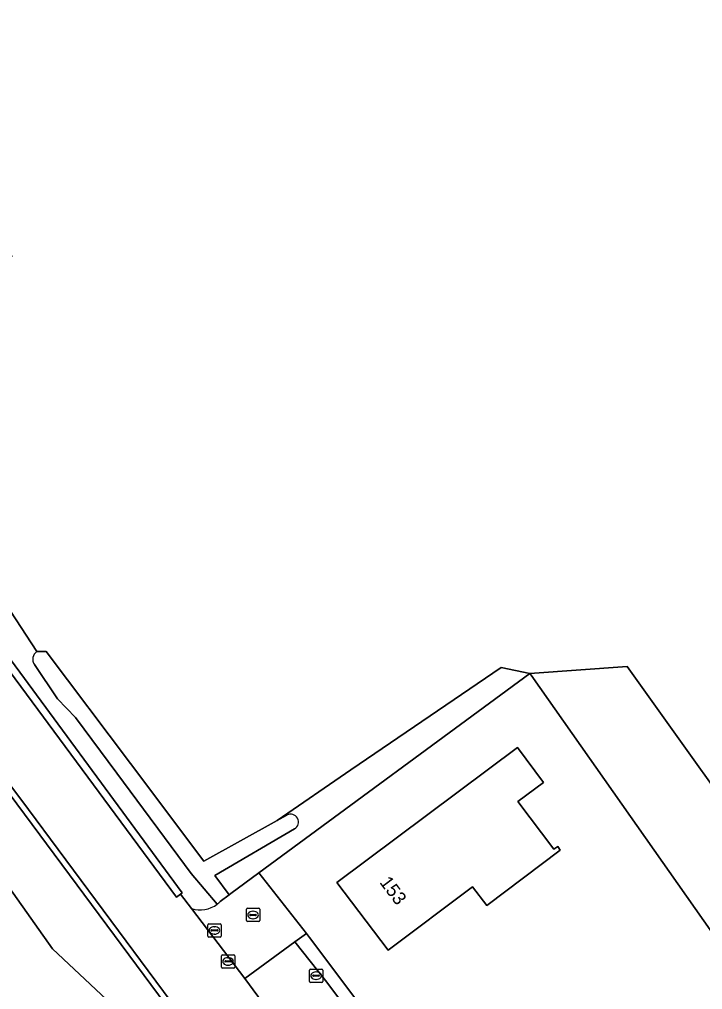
# Model space of a CAD drawing. Extents: x 164494 to 166241, y 382475 to 384495.
# Drawn here: x 164967.7 to 165019, y 383260.4 to 383333.2 of the extents above; entities that cross this region are included whole.
import ezdxf

# ---------------------------------------------------------------- set-up
doc = ezdxf.new("R2010")
doc.units = 0
for name, color, linetype in [('IMGEO_Berm_halfverhard', 7, 'Continuous'), ('IMGEO_Bouwland', 7, 'Continuous'), ('IMGEO_Brandkraan', 7, 'Continuous'), ('IMGEO_Erf', 7, 'Continuous'), ('IMGEO_Grasland_overig', 7, 'Continuous'), ('IMGEO_Groenvoorziening', 7, 'Continuous'), ('IMGEO_Kolk', 7, 'Continuous'), ('IMGEO_Pand', 7, 'Continuous'), ('IMGEO_Pand_nummerreeks', 7, 'Continuous'), ('IMGEO_Parkeervlak_open', 7, 'Continuous'), ('IMGEO_Rijbaan_lokaal_gesloten', 7, 'Continuous'), ('IMGEO_Rioolput', 7, 'Continuous'), ('IMGEO_Voetpad_open', 7, 'Continuous'), ('IMGEO_Waterloop', 7, 'Continuous')]:
    doc.layers.add(name, color=color, linetype=linetype)

msp = doc.modelspace()

# ---------------------------------------------------------------- linework, layer by layer
at = {"layer": 'IMGEO_Berm_halfverhard'}
for points in [[(164963.99, 383288.228), (164979.462, 383267.349), (164979.765, 383267.573), (164979.896, 383267.671), (164964.472, 383288.585)], [(164958.624, 383286.837), (164958.165, 383286.487), (164958.551, 383285.995), (164958.685, 383286.071), (164960.201, 383284.12), (164981.497, 383255.445), (165004.699, 383224.274), (165010.162, 383216.934), (165012.663, 383213.574), (165041.519, 383174.67), (165059.934, 383149.875), (165074.189, 383130.821), (165074.54, 383131.069), (165010.834, 383216.638), (165007.308, 383221.332), (165004.939, 383224.601), (164967.779, 383274.687)]]:
    msp.add_lwpolyline(points, close=True, dxfattribs=at)
at = {"layer": 'IMGEO_Bouwland'}
msp.add_lwpolyline([(164957.606, 383341.995), (164967.101, 383315.443), (164955.054, 383305.726), (164967.059, 383289.542), (164967.017, 383288.822), (164968.991, 383285.777), (164969.684, 383285.794), (164976.01, 383277.378), (164981.526, 383270.039), (164987.027, 383273.084), (164992.552, 383276.899), (165003.844, 383284.575), (165005.994, 383284.124), (165013.312, 383284.652), (165024.637, 383268.794)], dxfattribs=at)
at = {"layer": 'IMGEO_Brandkraan'}
for p, q in [((164989.523, 383261.941), (164990.375, 383261.941)), ((164989.448, 383261.015), (164989.448, 383261.867)), ((164989.707, 383261.435), (164989.707, 383261.447)), ((164990.145, 383261.398), (164989.747, 383261.398)), ((164989.75, 383261.484), (164990.148, 383261.484)), ((164989.936, 383261.721), (164989.961, 383261.721)), ((164990.191, 383261.447), (164990.191, 383261.435)), ((164990.449, 383261.867), (164990.449, 383261.015)), ((164990.375, 383260.941), (164989.523, 383260.941)), ((164989.959, 383261.161), (164989.934, 383261.161))]:
    msp.add_line(p, q, dxfattribs=at)
for points in [[(164989.523, 383261.941), (164990.375, 383261.941)], [(164989.448, 383261.015), (164989.448, 383261.867)], [(164990.449, 383261.867), (164990.449, 383261.015)], [(164990.375, 383260.941), (164989.523, 383260.941)]]:
    msp.add_lwpolyline(points, dxfattribs=at)
for centre, radius, start, end in [((164989.525, 383261.865), 0.0765, 91.55205, 178.44795), ((164989.525, 383261.865), 0.0765, 91.55205, 178.44795), ((164990.373, 383261.865), 0.0765, 1.55205, 88.44795), ((164990.373, 383261.865), 0.0765, 1.55205, 88.44795), ((164989.747, 383261.444), 0.0403, 85.87752, 175.75265), ((164989.744, 383261.434), 0.0366, 178.93798, 274.71019), ((164990.148, 383261.441), 0.043, 264.86636, 352.45326), ((164990.152, 383261.446), 0.0386, 1.73085, 96.63898), ((164989.525, 383261.017), 0.0765, 181.55205, 268.44795), ((164989.525, 383261.017), 0.0765, 181.55205, 268.44795), ((164990.373, 383261.017), 0.0765, 271.55205, 358.44795), ((164990.373, 383261.017), 0.0765, 271.55205, 358.44795)]:
    msp.add_arc(centre, radius, start, end, dxfattribs=at)
for centre, major_axis, ratio, start_param, end_param in [((164989.935, 383261.441), (-0.387, 0.002), 0.722429, 4.712389, 7.853982), ((164989.96, 383261.441), (-0.39, 0.002), 0.717154, 1.570796, 4.712389)]:
    msp.add_ellipse(centre, major_axis=major_axis, ratio=ratio, start_param=start_param, end_param=end_param, dxfattribs=at)
at = {"layer": 'IMGEO_Erf'}
msp.add_lwpolyline([(165023.92, 383258.647), (165006.085, 383283.995), (165005.994, 383284.124), (164985.66, 383269.156), (164989.232, 383264.617), (164989.466, 383264.319), (165007.637, 383240.088), (165012.902, 383233.067), (165015.239, 383229.95), (165031.244, 383208.7)], dxfattribs=at)
for points in [[(165002.759, 383266.706), (165001.688, 383268.124), (164995.36, 383263.347), (164991.508, 383268.448), (165005.068, 383278.566), (165007.024, 383275.946), (165005.104, 383274.513), (165007.808, 383270.93), (165008.087, 383271.141), (165008.286, 383270.878)], [(164975.852, 383258.131), (164970.169, 383263.46), (164965.557, 383269.946), (164955.812, 383263.214), (164956.735, 383261.945), (164963.02, 383266.55), (164966.969, 383261.241), (164960.49, 383256.476), (164961.549, 383255.02), (164957.546, 383252.108), (164954.876, 383255.779), (164951.664, 383260.196), (164937.061, 383250), (164897.833, 383222.545), (164900.712, 383215.89), (164901.156, 383214.863), (164940.067, 383238.056), (164950.373, 383219.454), (164986.059, 383239.833)]]:
    msp.add_lwpolyline(points, close=True, dxfattribs=at)
at = {"layer": 'IMGEO_Grasland_overig'}
for points in [[(165005.994, 383284.124), (165003.844, 383284.575), (164992.552, 383276.899), (164987.027, 383273.084), (164987.757, 383273.488)], [(164988.339, 383272.465), (164982.336, 383268.962), (164983.426, 383267.512), (164983.55, 383267.603), (164985.66, 383269.156), (165005.994, 383284.124)]]:
    msp.add_lwpolyline(points, dxfattribs=at)
msp.add_lwpolyline([(165005.994, 383284.124), (165006.085, 383283.995), (165023.92, 383258.647), (165029.151, 383261.419), (165024.637, 383268.794), (165013.312, 383284.652)], close=True, dxfattribs=at)
msp.add_arc((164988.043, 383272.973), 0.589, 300.24192, 119.03047, dxfattribs=at)
at = {"layer": 'IMGEO_Groenvoorziening'}
for points in [[(164947.016, 383302.564), (164946.531, 383302.21), (164898.891, 383366.181), (164896.813, 383364.002), (164902.872, 383356.577), (164911.399, 383344.917), (164923.309, 383329.117), (164956.871, 383285.126), (164961.245, 383279.38), (164965.055, 383274.376), (164963.613, 383272.68), (164965.557, 383269.946), (164970.169, 383263.46), (164975.852, 383258.131), (164986.059, 383239.833), (164986.709, 383240.204), (164987.609, 383238.932), (164987.636, 383240.128), (164988.453, 383240.018), (165001.41, 383221.726)], [(164931.465, 383338.015), (164929.545, 383340.596), (164929.058, 383339.863), (164927.659, 383338.025), (164950.049, 383307.989), (164949.568, 383307.631), (164951.985, 383304.388), (164961.639, 383291.401), (164963.99, 383288.228), (164964.472, 383288.585), (164979.896, 383267.671), (164979.765, 383267.573), (164980.598, 383266.49)], [(165000.462, 383220.634), (165001.447, 383219.83), (165002.516, 383221.297), (165004.699, 383224.274), (164981.497, 383255.445), (164960.201, 383284.12), (164958.685, 383286.071), (164958.551, 383285.995), (164958.165, 383286.487), (164958.624, 383286.837), (164957.498, 383288.332), (164947.902, 383301.374), (164947.016, 383302.564)], [(164968.991, 383285.777), (164967.017, 383288.822)], [(164982.523, 383266.812), (164980.571, 383269.111), (164974.985, 383276.643), (164971.879, 383280.831), (164970.542, 383282.234), (164968.808, 383284.798)]]:
    msp.add_lwpolyline(points, dxfattribs=at)
msp.add_lwpolyline([(164984.609, 383261.224), (165002.791, 383236.502), (165006.841, 383239.499), (164990.657, 383261.092), (164988.359, 383263.977)], close=True, dxfattribs=at)
for centre, radius, start, end in [((164969.36, 383285.201), 0.684, 122.6776, 216.1467), ((164981.262, 383268.436), 2.056, 251.16033, 307.83188)]:
    msp.add_arc(centre, radius, start, end, dxfattribs=at)
at = {"layer": 'IMGEO_Kolk'}
for p, q in [((164982.84, 383262.088), (164982.84, 383262.94)), ((164982.915, 383263.014), (164983.767, 383263.014)), ((164983.328, 383262.794), (164983.353, 383262.794)), ((164983.841, 383262.94), (164983.841, 383262.088)), ((164983.767, 383262.014), (164982.915, 383262.014)), ((164983.099, 383262.508), (164983.099, 383262.52)), ((164983.537, 383262.471), (164983.139, 383262.471)), ((164983.142, 383262.557), (164983.54, 383262.557)), ((164983.351, 383262.234), (164983.326, 383262.234)), ((164983.583, 383262.52), (164983.583, 383262.508))]:
    msp.add_line(p, q, dxfattribs=at)
for points in [[(164982.84, 383262.088), (164982.84, 383262.94)], [(164982.915, 383263.014), (164983.767, 383263.014)], [(164983.841, 383262.94), (164983.841, 383262.088)], [(164983.767, 383262.014), (164982.915, 383262.014)]]:
    msp.add_lwpolyline(points, dxfattribs=at)
for centre, radius, start, end in [((164982.917, 383262.938), 0.0765, 91.55205, 178.44795), ((164982.917, 383262.938), 0.0765, 91.55205, 178.44795), ((164983.765, 383262.938), 0.0765, 1.55205, 88.44795), ((164983.765, 383262.938), 0.0765, 1.55205, 88.44795), ((164982.917, 383262.09), 0.0765, 181.55205, 268.44795), ((164982.917, 383262.09), 0.0765, 181.55205, 268.44795), ((164983.139, 383262.517), 0.0403, 85.87752, 175.75265), ((164983.136, 383262.507), 0.0366, 178.93798, 274.71019), ((164983.54, 383262.514), 0.043, 264.86636, 352.45326), ((164983.544, 383262.519), 0.0386, 1.73085, 96.63898), ((164983.765, 383262.09), 0.0765, 271.55205, 358.44795), ((164983.765, 383262.09), 0.0765, 271.55205, 358.44795)]:
    msp.add_arc(centre, radius, start, end, dxfattribs=at)
for centre, major_axis, ratio, start_param, end_param in [((164983.327, 383262.514), (-0.387, 0.002), 0.722429, 4.712389, 7.853982), ((164983.352, 383262.514), (-0.39, 0.002), 0.717154, 1.570796, 4.712389)]:
    msp.add_ellipse(centre, major_axis=major_axis, ratio=ratio, start_param=start_param, end_param=end_param, dxfattribs=at)
at = {"layer": 'IMGEO_Pand'}
msp.add_lwpolyline([(165008.087, 383271.141), (165007.808, 383270.93), (165005.104, 383274.513), (165007.024, 383275.946), (165005.068, 383278.566), (164991.508, 383268.448), (164995.36, 383263.347), (165001.688, 383268.124), (165002.759, 383266.706), (165008.286, 383270.878)], close=True, dxfattribs=at)
at = {"layer": 'IMGEO_Parkeervlak_open'}
msp.add_lwpolyline([(164980.598, 383266.49), (164984.609, 383261.224), (164988.359, 383263.977), (164989.232, 383264.617), (164985.66, 383269.156), (164983.55, 383267.603), (164983.426, 383267.512), (164982.745, 383267.011)], dxfattribs=at)
for centre, radius, start, end in [((164981.404, 383268.283), 1.848, 307.24718, 316.49869), ((164981.262, 383268.436), 2.056, 251.16033, 307.83188)]:
    msp.add_arc(centre, radius, start, end, dxfattribs=at)
at = {"layer": 'IMGEO_Rijbaan_lokaal_gesloten'}
msp.add_lwpolyline([(165024.153, 383207.813), (165010.316, 383226.399), (165008.04, 383229.432), (165002.791, 383236.502), (164984.609, 383261.224), (164980.598, 383266.49), (164979.765, 383267.573), (164979.462, 383267.349), (164963.99, 383288.228), (164961.639, 383291.401), (164957.498, 383288.332), (164958.624, 383286.837), (164967.779, 383274.687), (165004.939, 383224.601), (165007.308, 383221.332), (165010.834, 383216.638), (165074.54, 383131.069)], dxfattribs=at)
at = {"layer": 'IMGEO_Rioolput'}
for p, q in [((164984.716, 383265.577), (164984.716, 383266.429)), ((164984.791, 383266.503), (164985.643, 383266.503)), ((164985.204, 383266.283), (164985.229, 383266.283)), ((164985.717, 383266.429), (164985.717, 383265.577)), ((164984.975, 383265.997), (164984.975, 383266.009)), ((164985.413, 383265.96), (164985.015, 383265.96)), ((164985.018, 383266.046), (164985.416, 383266.046)), ((164985.227, 383265.723), (164985.202, 383265.723)), ((164985.459, 383266.009), (164985.459, 383265.997)), ((164981.817, 383264.417), (164981.817, 383265.269)), ((164981.892, 383265.343), (164982.744, 383265.343)), ((164982.076, 383264.837), (164982.076, 383264.849)), ((164982.119, 383264.886), (164982.517, 383264.886)), ((164982.305, 383265.123), (164982.33, 383265.123)), ((164982.56, 383264.849), (164982.56, 383264.837)), ((164982.818, 383265.269), (164982.818, 383264.417)), ((164985.643, 383265.503), (164984.791, 383265.503)), ((164982.744, 383264.343), (164981.892, 383264.343)), ((164982.514, 383264.8), (164982.116, 383264.8)), ((164982.328, 383264.563), (164982.303, 383264.563))]:
    msp.add_line(p, q, dxfattribs=at)
for points in [[(164984.716, 383265.577), (164984.716, 383266.429)], [(164984.791, 383266.503), (164985.643, 383266.503)], [(164985.717, 383266.429), (164985.717, 383265.577)], [(164981.817, 383264.417), (164981.817, 383265.269)], [(164981.892, 383265.343), (164982.744, 383265.343)], [(164982.818, 383265.269), (164982.818, 383264.417)], [(164985.643, 383265.503), (164984.791, 383265.503)], [(164982.744, 383264.343), (164981.892, 383264.343)]]:
    msp.add_lwpolyline(points, dxfattribs=at)
for centre, radius, start, end in [((164984.793, 383266.427), 0.0765, 91.55205, 178.44795), ((164984.793, 383266.427), 0.0765, 91.55205, 178.44795), ((164985.641, 383266.427), 0.0765, 1.55205, 88.44795), ((164985.641, 383266.427), 0.0765, 1.55205, 88.44795), ((164984.793, 383265.579), 0.0765, 181.55205, 268.44795), ((164984.793, 383265.579), 0.0765, 181.55205, 268.44795), ((164985.015, 383266.006), 0.0403, 85.87752, 175.75265), ((164985.012, 383265.996), 0.0366, 178.93798, 274.71019), ((164985.416, 383266.003), 0.043, 264.86636, 352.45326), ((164985.42, 383266.008), 0.0386, 1.73085, 96.63898), ((164985.641, 383265.579), 0.0765, 271.55205, 358.44795), ((164985.641, 383265.579), 0.0765, 271.55205, 358.44795), ((164981.894, 383265.267), 0.0765, 91.55205, 178.44795), ((164981.894, 383265.267), 0.0765, 91.55205, 178.44795), ((164982.116, 383264.846), 0.0403, 85.87752, 175.75265), ((164982.113, 383264.836), 0.0366, 178.93798, 274.71019), ((164982.517, 383264.843), 0.043, 264.86636, 352.45326), ((164982.521, 383264.848), 0.0386, 1.73085, 96.63898), ((164982.742, 383265.267), 0.0765, 1.55205, 88.44795), ((164982.742, 383265.267), 0.0765, 1.55205, 88.44795), ((164981.894, 383264.419), 0.0765, 181.55205, 268.44795), ((164981.894, 383264.419), 0.0765, 181.55205, 268.44795), ((164982.742, 383264.419), 0.0765, 271.55205, 358.44795), ((164982.742, 383264.419), 0.0765, 271.55205, 358.44795)]:
    msp.add_arc(centre, radius, start, end, dxfattribs=at)
for centre, major_axis, ratio, start_param, end_param in [((164985.203, 383266.003), (-0.387, 0.002), 0.722429, 4.712389, 7.853982), ((164985.228, 383266.003), (-0.39, 0.002), 0.717154, 1.570796, 4.712389), ((164982.304, 383264.843), (-0.387, 0.002), 0.722429, 4.712389, 7.853982), ((164982.329, 383264.843), (-0.39, 0.002), 0.717154, 1.570796, 4.712389)]:
    msp.add_ellipse(centre, major_axis=major_axis, ratio=ratio, start_param=start_param, end_param=end_param, dxfattribs=at)
at = {"layer": 'IMGEO_Voetpad_open'}
msp.add_lwpolyline([(165007.637, 383240.088), (164989.466, 383264.319), (164989.232, 383264.617), (164988.359, 383263.977), (164990.657, 383261.092), (165006.841, 383239.499)], close=True, dxfattribs=at)
at = {"layer": 'IMGEO_Waterloop'}
for points in [[(164976.01, 383277.378), (164969.684, 383285.794), (164968.991, 383285.777)], [(164968.808, 383284.798), (164970.542, 383282.234), (164971.879, 383280.831), (164974.985, 383276.643), (164980.571, 383269.111), (164982.523, 383266.812)], [(164987.757, 383273.488), (164987.027, 383273.084), (164981.526, 383270.039), (164976.01, 383277.378)], [(164982.745, 383267.011), (164983.426, 383267.512), (164982.336, 383268.962), (164988.339, 383272.465)]]:
    msp.add_lwpolyline(points, dxfattribs=at)
for centre, radius, start, end in [((164969.36, 383285.201), 0.684, 122.6776, 216.1467), ((164988.043, 383272.973), 0.589, 300.24192, 119.03047), ((164981.404, 383268.283), 1.848, 307.24718, 316.49869)]:
    msp.add_arc(centre, radius, start, end, dxfattribs=at)

# ---------------------------------------------------------------- texts
at = {"layer": 'IMGEO_Pand_nummerreeks'}
msp.add_text('153', height=1, rotation=307.04724, dxfattribs=at).set_placement((164994.672, 383268.441))

doc.saveas('drawing.dxf')
